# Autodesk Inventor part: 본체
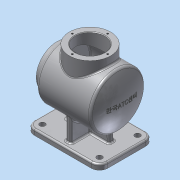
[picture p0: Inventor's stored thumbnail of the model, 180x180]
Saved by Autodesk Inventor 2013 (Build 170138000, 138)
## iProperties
Created: 2016-09
Part Number: 본체
Material: 알루미늄 6061
Document SubType Name: Modeling
Designer: dgall
Mass: 973.911 g
Surface Area: 1287.1 cm^2
Volume: 359.377 cm^3
Density: 2.71 g/cm^3
Author: dgall
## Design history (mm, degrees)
sketch "스케치1"
  geometry: L1 (-67.5, 50)-(67.5, 50); L2 (67.5, 50)-(67.5, -50); L3 (67.5, -50)-(-67.5, -50); L4 (-67.5, -50)-(-67.5, 50); 1 further point
  constraints: 8 end point, 2 parallel, 1 horizontal, 1 perpendicular
  dimensions: "d0" = 135 distance of L1.start L1.end; "d2" = 100 distance of L1.end L2.end; "d3" = 50 vertical distance of point (0, 0) L1.end; "d4" = 67.5 horizontal distance of point (0, 0) L1.start (= 0.5 x d0)
extrude "돌출1" new body sketch "스케치1" distance "d5" = 10; taper "d6" = 0 deg
fillet "모깎기1" dims "d7" = 15
sketch "스케치2"
  geometry: C1 r 5 at (-52.5, 35); C2 r 5 at (52.5, 35); C3 r 5 at (52.5, -35); C4 r 5 at (-52.5, -35); A1 r 15 centre (-52.5, 35) between (-52.5, 50) and (-67.5, 35) reference; A2 r 15 centre (-52.5, -35) between (-67.5, -35) and (-52.5, -50) reference; A3 r 15 centre (52.5, -35) between (52.5, -50) and (67.5, -35) reference; A4 r 15 centre (52.5, 35) between (67.5, 35) and (52.5, 50) reference; 1 further point
  constraints: 4 centre point, 4 coincident
  dimensions: "d8" = 10 diameter of C1; "d10" = 10 diameter of C2; "d11" = 10 diameter of C3; "d12" = 10 diameter of C4
extrude "돌출2" cut sketch "스케치2" stored distance "d13" = 10; taper "d14" = 0 deg
node "작업 평면1"
sketch "스케치3"
  geometry: L1 (-67.5, 35)-(-67.5, -35) reference; L2 (-61, 0)-(61, 0); L3 (-61, 0)-(-61, 38); L4 (-61, 38)-(-49, 38); L5 (-49, 38)-(-49, 50); L6 (-49, 50)-(50.283, 50); A1 r 122 centre (-61, 0) between (61, 0) and (50.283, 50); 1 further point
  constraints: 10 end point, 4 perpendicular, 2 point on circle, 1 centre point, 1 coincident, 1 parallel
  dimensions: "d16" = 0 distance from line of L2 point (0, 0); "d17" = 122 distance of L2.start L2.end; "d18" = 6.5 distance from line of L1 L2.start; "d20" = 76 diameter of L4 L2; "d21" = 100 diameter of L6 L2; "d22" = 12 distance of L3.end L4.end
revolve "회전1" sketch "스케치3" stored, may be unused: angle "d23" = 90 deg
sketch "스케치4"
  geometry: C1 r 38 at (0, 0) reference; C2 r 27 at (0, 0); 1 further point
  constraints: 1 centre point, 1 coincident
  dimensions: "d24" = 54 diameter of C2
extrude "돌출3" cut sketch "스케치4" distance "d26" = 15; taper "d27" = 0 deg
chamfer "모따기1" distance "d28" = 1; stored, may be unused: second distance "d29" = 2, angle "d30" = 45 deg
sketch "스케치5" dims "d31" = 65
  geometry: L1 (0, 0)-(32.5, 0); C1 r 28 at (0, 0) reference; 1 further point
  constraints: 2 end point, 1 coincident, 1 horizontal, 1 horizontal alignment, 2 other
hole "구멍1" sketch "스케치5" at (32.5, 0) diameter "d33" = 3.242; stored, may be unused: countersink angle "d37" = 90 deg, drill point angle "d39" = 118 deg; dims "d34" = 8, "d35" = 4, "d36" = 2, "d38" = 10
fillet "모깎기2" dims "d43" = 5
node "작업 평면2"
fillet "모깎기3" dims "d50" = 3
fillet "모깎기4" dims "d51" = 3
node "작업 평면3"
sketch "스케치8"
  geometry: L1 (-29.035, 87.491)-(29.035, 87.491); L2 (29.035, 87.491)-(29.035, 76.509); L3 (29.035, 76.509)-(-29.035, 76.509); L4 (-29.035, 76.509)-(-29.035, 87.491); L5 (-29.035, 82)-(29.035, 82); L6 (0, 87.491)-(0, 76.509); L7 (50, 0)-(35, 0) reference; C1 r 50 at (0, 82) reference; 1 further point
  constraints: 4 end point, 4 midpoint, 2 other
  dimensions: "d65" = 0 horizontal distance of point (0, 0) L6.end; "d66" = 82 distance from line of L7 L5.end
feature "엠보싱1" sketch "스케치8" dims "d67" = 0.5, "d68" = 0
sketch "스케치9"
  geometry: L1 (46, 109)-(46, 55) reference; L2 (61, 54)-(61, 110) reference; L3 (61, 82)-(-90, 82); L4 (-48.325, 129)-(46, 129); L5 (46, 129)-(46, 82); L6 (46, 82)-(-58, 82); A1 r 122 centre (61, 82) between (-50.283, 132) and (-50.283, 32) reference; A2 r 119 centre (61, 82) between (-48.325, 129) and (-58, 82); 1 further point
  constraints: 8 end point, 2 midpoint, 2 point on circle, 2 point on line, 1 centre point, 1 collinear, 1 parallel, 1 perpendicular
  dimensions: "d69" = 3 radial gap between concentric circles of A1 A2; "d71" = 94 diameter of L4 L3
revolve "회전2" sketch "스케치9" stored, may be unused: angle "d72" = 90 deg
sketch "스케치12"
  geometry: L1 (-5, 40)-(5, 40); L2 (5, 40)-(5, -40); L3 (5, -40)-(-5, -40); L4 (-5, -40)-(-5, 40); L5 (0, 40)-(0, -40); L6 (-5, 0)-(5, 0); L7 (52.5, 50)-(-52.5, 50) reference; 1 further point
  constraints: 12 end point, 4 midpoint, 2 parallel, 1 horizontal, 1 perpendicular
  dimensions: "d73" = 10 distance of L1.start L1.end; "d75" = 5 horizontal distance of point (0, 0) L1.start; "d76" = 50 distance from line of L6.end L7; "d77" = 80 distance of L3.end L1.start
extrude "돌출5" join sketch "스케치12" stored distance "d78" = 15; taper "d79" = 0 deg
sketch "스케치13"
  geometry: L1 (44, 32)-(-50.283, 32) reference; L2 (52.5, 10)-(-52.5, 10) reference; L3 (52.5, 10)-(64.5, 10) reference; L4 (47.5, 10)-(57.5, 10) reference; L5 (38.075, 32)-(40, 10); 1 further point
  constraints: 2 end point, 2 point on line
  dimensions: "d80" = 95 deg angle of L5 L2; "d81" = 40 horizontal distance of point (0, 0) L5.end
feature "리브1" sketch "스케치13" dims "d82" = 1, "d83" = 10, "d84" = 0, "d85" = 0, "d86" = 1, "d87" = 1
sketch "스케치14"
  geometry: L1 (44, 32)-(-50.283, 32) reference; L2 (52.5, 10)-(-52.5, 10) reference; L3 (-38.075, 32)-(-40, 10); 1 further point
  constraints: 2 end point, 2 point on line
  dimensions: "d88" = 95 deg angle of L3 L2; "d89" = 40 horizontal distance of point (0, 0) L3.end
feature "리브2" sketch "스케치14" dims "d90" = 1, "d91" = 10, "d92" = 0, "d93" = 0, "d94" = 1, "d95" = 1
fillet "모깎기5" dims "d96" = 3
fillet "모깎기6" dims "d97" = 3
fillet "모깎기7" dims "d102" = 3
fillet "모깎기8" dims "d103" = 5
fillet "모깎기9" dims "d104" = 2
fillet "모깎기10" dims "d105" = 2
node "작업 평면4"
sketch "스케치17"
  geometry: L1 (-67.5, 35)-(-67.5, -35) reference; L2 (-67.5, 0)-(0, 0); C1 r 38 at (0, 0); 1 further point
  constraints: 2 end point, 1 centre point, 1 coincident, 1 midpoint, 1 perpendicular
  dimensions: "d110" = 67.5 distance of L2.start L2.end; "d112" = 76 diameter of C1
extrude "돌출7" join sketch "스케치17" stored distance "d113" = 15; taper "d114" = 0 deg
fillet "모깎기11" dims "d115" = 3
sketch "스케치18"
  geometry: C1 r 38 at (0, 0) reference; C2 r 27 at (0, 0)
  constraints: 1 centre point, 1 coincident
  dimensions: "d116" = 54 diameter of C2
extrude "돌출8" cut sketch "스케치18" stored distance "d118" = 15; taper "d119" = 0 deg
sketch "스케치19" dims "d120" = 65
  geometry: L1 (0, 0)-(0, 32.5); C1 r 38 at (0, 0) reference
  constraints: 2 end point, 1 coincident, 1 vertical, 1 vertical alignment, 2 other
hole "구멍3" sketch "스케치19" at (0, 32.5) diameter "d122" = 3.242; stored, may be unused: countersink angle "d126" = 90 deg, drill point angle "d128" = 118 deg; dims "d123" = 8, "d124" = 4, "d125" = 2, "d127" = 10
chamfer "모따기3" distance "d132" = 1; stored, may be unused: second distance "d133" = 2, angle "d134" = 45 deg
node "솔리드1"
pattern_circular "원형 패턴1" dims angle "d41" = 360 deg
pattern_circular "원형 패턴3" dims angle "d130" = 360 deg
other parameters: "d15" = 82, "d44" = 147, "d64" = 105.25, "d109" = 147
